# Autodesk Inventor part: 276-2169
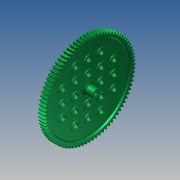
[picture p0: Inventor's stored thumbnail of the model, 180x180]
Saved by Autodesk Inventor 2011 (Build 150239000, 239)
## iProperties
Created: 2010-04
Part Number: 276-2169
Material: ABS Plastic
Document SubType Name: Modeling
Designer: Autodesk Inc.
Categories: <?xml version="1.0" encoding="UTF-16"?> <MemberInstance><Categories><FamilyTemplate><FamilyTemplateParameter ValueType="xs:double" Id="1" ObjectReferenceKey="da
Mass: 20.4005 g
Surface Area: 204.791 cm^2
Volume: 19.2457 cm^3
Density: 1.06 g/cm^3
Catalog Web Link: http://www.vexrobotics.com/products/accessories/motion/276-2169.html
Description: This kit contains four sizes of VEX Spur Gears (12-, 36-, 60-, and 84-tooth gears). The 60- and 84-tooth gears have extra mount
Vendor: Innovation First, Inc.
CustomPartVersion: 1
Company: Autodesk Inc.
Author: Autodesk Inc.
Title: VEX Robotics Kit of Parts
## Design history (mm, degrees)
sketch "Sketch1"
  geometry: C1 r 45.297 at (0, 0)
  constraints: 1 centre point
  dimensions: "d0" = 90.59333 diameter of C1 (= da_da)
extrude "Extrusion1" new body sketch "Sketch1" distance "d1" = 6.35 (= da_b); taper "d2" = 0 deg
sketch "Sketch2"
  geometry: C1 r 45.297 at (0, 0) reference; C2 r 44.45 at (0, 0)
  constraints: 1 centre point, 1 coincident
  dimensions: "d3" = 88.9 diameter of C2 (= da_dw)
feature "Pitch Diameter" sketch "Sketch2" dims "d4" = 76.2, "d5" = 0
workplane "Work Plane1"
workplane "Work Plane2"
workplane "Work Plane3"
feature "Spur Gear" dims "da_b" = 6.35, "da_d" = 88.9, "da_aw" = 50.8, "da_da" = 90.59333, "da_df" = 85.83083, "da_dw" = 88.9, angle "da_beta" = 0 deg, "da_lefttooth" = 0, "da_righttooth" = 0
sketch "Sketch3"
  geometry: C1 r 40.996 at (0, 0); A1 r 45.297 centre (0, 0) between (-2.963, 45.2) and (-3.807, 45.136) reference
  constraints: 1 centre point, 1 coincident
  dimensions: "d20" = 81.9912 diameter of C1
extrude "Extrusion2" cut sketch "Sketch3" distance "d21" = 1.9304; taper "d22" = -10 deg
workplane "Work Plane4"
fillet "Fillet1" dims "d23" = 0.9906
mirror "Mirror1"
sketch "Sketch4"
  geometry: C1 r 39.824 at (0, 0) reference; C2 r 4.178 at (0, -25.4)
  constraints: 1 centre point, 1 vertical alignment
  dimensions: "d24" = 8.3566 diameter of C2; "d25" = 25.4 distance of C2.centre C1.centre
extrude "Extrusion3" join sketch "Sketch4" distance "d26" = 0.9144; taper "d27" = 0 deg
sketch "Sketch5"
  geometry: C1 r 39.824 at (0, 0) reference; C2 r 5.88 at (-4.125, -25.4)
  constraints: 1 centre point
  dimensions: "d28" = 11.7602 diameter of C2; "d29" = 25.4 vertical distance of C1.centre C2.centre
extrude "Extrusion4" join sketch "Sketch5" distance "d30" = 1.9304; taper "d31" = 0 deg
sketch "Sketch6"
  geometry: C1 r 5.88 at (0, 0) reference; C2 r 4.674 at (0, 0); 1 further point
  constraints: 1 centre point, 1 coincident
  dimensions: "d32" = 9.3472 diameter of C2
extrude "Extrusion5" cut sketch "Sketch6" distance "d33" = 2.9972; taper "d34" = 0 deg
sketch "Sketch7"
  geometry: C1 r 4.178 at (0, 0) reference; 1 further point
hole "Hole1" sketch "Sketch7" at (0, 0) diameter "d35" = 4.3434; stored, may be unused: countersink angle "d39" = 82 deg, drill point angle "d41" = 118 deg; dims "d36" = 19.05, "d37" = 9.525, "d38" = 6.35, "d40" = 25.4
sketch "Sketch8"
  geometry: C1 r 39.824 at (0, 0) reference; C2 r 4.001 at (0, 0)
  constraints: 1 centre point, 1 coincident
  dimensions: "d48" = 8.001 diameter of C2
extrude "Extrusion6" join sketch "Sketch8" distance "d49" = 8.2804; taper "d50" = 0 deg
sketch "Sketch9"
  geometry: C1 r 39.824 at (0, 0) reference; C2 r 4.001 at (0, 0)
  constraints: 1 centre point, 1 coincident
  dimensions: "d51" = 8.001 diameter of C2
extrude "Extrusion7" join sketch "Sketch9" distance "d52" = 1.9304; taper "d53" = 0 deg
chamfer "Chamfer1" distance "d54" = 1.524; stored, may be unused: second distance "d55" = 3.175, angle "d56" = 45 deg
sketch "Sketch10"
  geometry: L1 (1.612, 0.952)-(1.558, 1.007); L2 (1.558, 1.025)-(1.612, 1.079); L3 (1.612, 1.104)-(1.612, 1.079); L4 (1.558, 1.177)-(1.612, 1.231); L5 (1.612, 1.362)-(1.612, 1.231); L6 (1.232, 1.612)-(1.177, 1.558); L7 (1.159, 1.558)-(1.105, 1.612); L8 (1.079, 1.612)-(1.105, 1.612); L9 (1.232, 1.612)-(1.362, 1.612); L10 (1.612, 0.952)-(1.612, -0.952); L11 (1.558, -1.007)-(1.612, -0.952); L12 (1.612, 1.104)-(1.558, 1.159); L13 (1.079, 1.612)-(1.025, 1.558); L14 (-1.362, 1.612)-(-1.231, 1.612); L15 (-1.177, 1.558)-(-1.231, 1.612); L16 (1.007, 1.558)-(0.952, 1.612); L17 (-0.952, 1.613)-(0.952, 1.612); L18 (-0.952, 1.613)-(-1.007, 1.558); L19 (-1.024, 1.558)-(-1.079, 1.612); L20 (-1.104, 1.613)-(-1.079, 1.612); L21 (-1.104, 1.613)-(-1.159, 1.558); L22 (1.613, -1.079)-(1.558, -1.024); L23 (1.613, -1.079)-(1.612, -1.105); L24 (1.558, -1.159)-(1.612, -1.105); L25 (1.613, -1.231)-(1.558, -1.177); L26 (1.613, -1.231)-(1.612, -1.362); L27 (1.362, -1.612)-(1.231, -1.612); L28 (1.177, -1.558)-(1.231, -1.612); L29 (1.104, -1.613)-(1.079, -1.612); L30 (1.024, -1.558)-(1.079, -1.612); L31 (0.952, -1.613)-(1.007, -1.558); L32 (0.952, -1.613)-(-0.952, -1.612); L33 (1.104, -1.613)-(1.159, -1.558); L34 (-1.007, -1.558)-(-0.952, -1.612); L35 (-1.079, -1.612)-(-1.025, -1.558); L36 (-1.079, -1.612)-(-1.105, -1.612); L37 (-1.159, -1.558)-(-1.105, -1.612); L38 (-1.232, -1.612)-(-1.177, -1.558); L39 (-1.612, -0.952)-(-1.558, -1.007); L40 (-1.558, -1.025)-(-1.612, -1.079); L41 (-1.612, -1.104)-(-1.612, -1.079); L42 (-1.612, -1.104)-(-1.558, -1.159); L43 (-1.558, -1.177)-(-1.612, -1.231); L44 (-1.612, -1.362)-(-1.612, -1.231); L45 (-1.232, -1.612)-(-1.362, -1.612); L46 (-1.612, -0.952)-(-1.612, 0.952); L47 (-1.558, 1.007)-(-1.612, 0.952); L48 (-1.613, 1.079)-(-1.558, 1.024); L49 (-1.613, 1.079)-(-1.612, 1.105); L50 (-1.558, 1.159)-(-1.612, 1.105); L51 (-1.613, 1.231)-(-1.558, 1.177); L52 (-1.613, 1.231)-(-1.612, 1.362); A1 r 0.013 centre (1.567, 1.016) between (1.558, 1.025) and (1.558, 1.007); A2 r 0.013 centre (1.567, 1.168) between (1.558, 1.177) and (1.558, 1.159); A3 r 0.25 centre (1.362, 1.362) between (1.612, 1.362) and (1.362, 1.612); A4 r 0.013 centre (1.168, 1.567) between (1.159, 1.558) and (1.177, 1.558); A5 r 0.012 centre (-1.016, 1.566) between (-1.024, 1.558) and (-1.007, 1.558); A6 r 0.012 centre (-1.168, 1.566) between (-1.177, 1.558) and (-1.159, 1.558); A7 r 0.013 centre (1.016, 1.567) between (1.007, 1.558) and (1.025, 1.558); A8 r 0.012 centre (1.566, -1.016) between (1.558, -1.007) and (1.558, -1.024); A9 r 0.013 centre (1.567, -1.168) between (1.558, -1.159) and (1.558, -1.177); A10 r 0.25 centre (1.362, -1.362) between (1.362, -1.612) and (1.612, -1.362); A11 r 0.012 centre (1.168, -1.566) between (1.177, -1.558) and (1.159, -1.558); A12 r 0.012 centre (1.016, -1.566) between (1.024, -1.558) and (1.007, -1.558); A13 r 0.013 centre (-1.016, -1.567) between (-1.007, -1.558) and (-1.025, -1.558); A14 r 0.013 centre (-1.168, -1.567) between (-1.159, -1.558) and (-1.177, -1.558); A15 r 0.013 centre (-1.567, -1.168) between (-1.558, -1.177) and (-1.558, -1.159); A16 r 0.013 centre (-1.567, -1.016) between (-1.558, -1.025) and (-1.558, -1.007); A17 r 0.25 centre (-1.362, -1.362) between (-1.612, -1.362) and (-1.362, -1.612); A18 r 0.25 centre (-1.362, 1.362) between (-1.362, 1.612) and (-1.612, 1.362); A19 r 0.013 centre (-1.567, 1.168) between (-1.558, 1.159) and (-1.558, 1.177); A20 r 0.012 centre (-1.566, 1.016) between (-1.558, 1.007) and (-1.558, 1.024); 1 further point
  constraints: 104 end point, 40 point on circle, 20 centre point
feature "iFeature2:1" sketch "Sketch10"
body "Solid1"
pattern_linear "Rectangular Pattern1" dims "d44" = 12.7, "d47" = 12.7
body "Srf1"
other parameters: "d6" = 0, "d7" = 0.374 (computed from da_z), "d9" = 0, "d14" = 0, "d15" = 50.8 (= da_aw), "d16" = 0, "d17" = 0, "d18" = 0, "d19" = 50.8 (= da_aw)
